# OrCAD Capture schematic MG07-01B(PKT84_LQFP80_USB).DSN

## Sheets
1 01. Adapter IF: size D; title: Adapter I/F; rev: 1.1; company: megawin; note: MG07-01
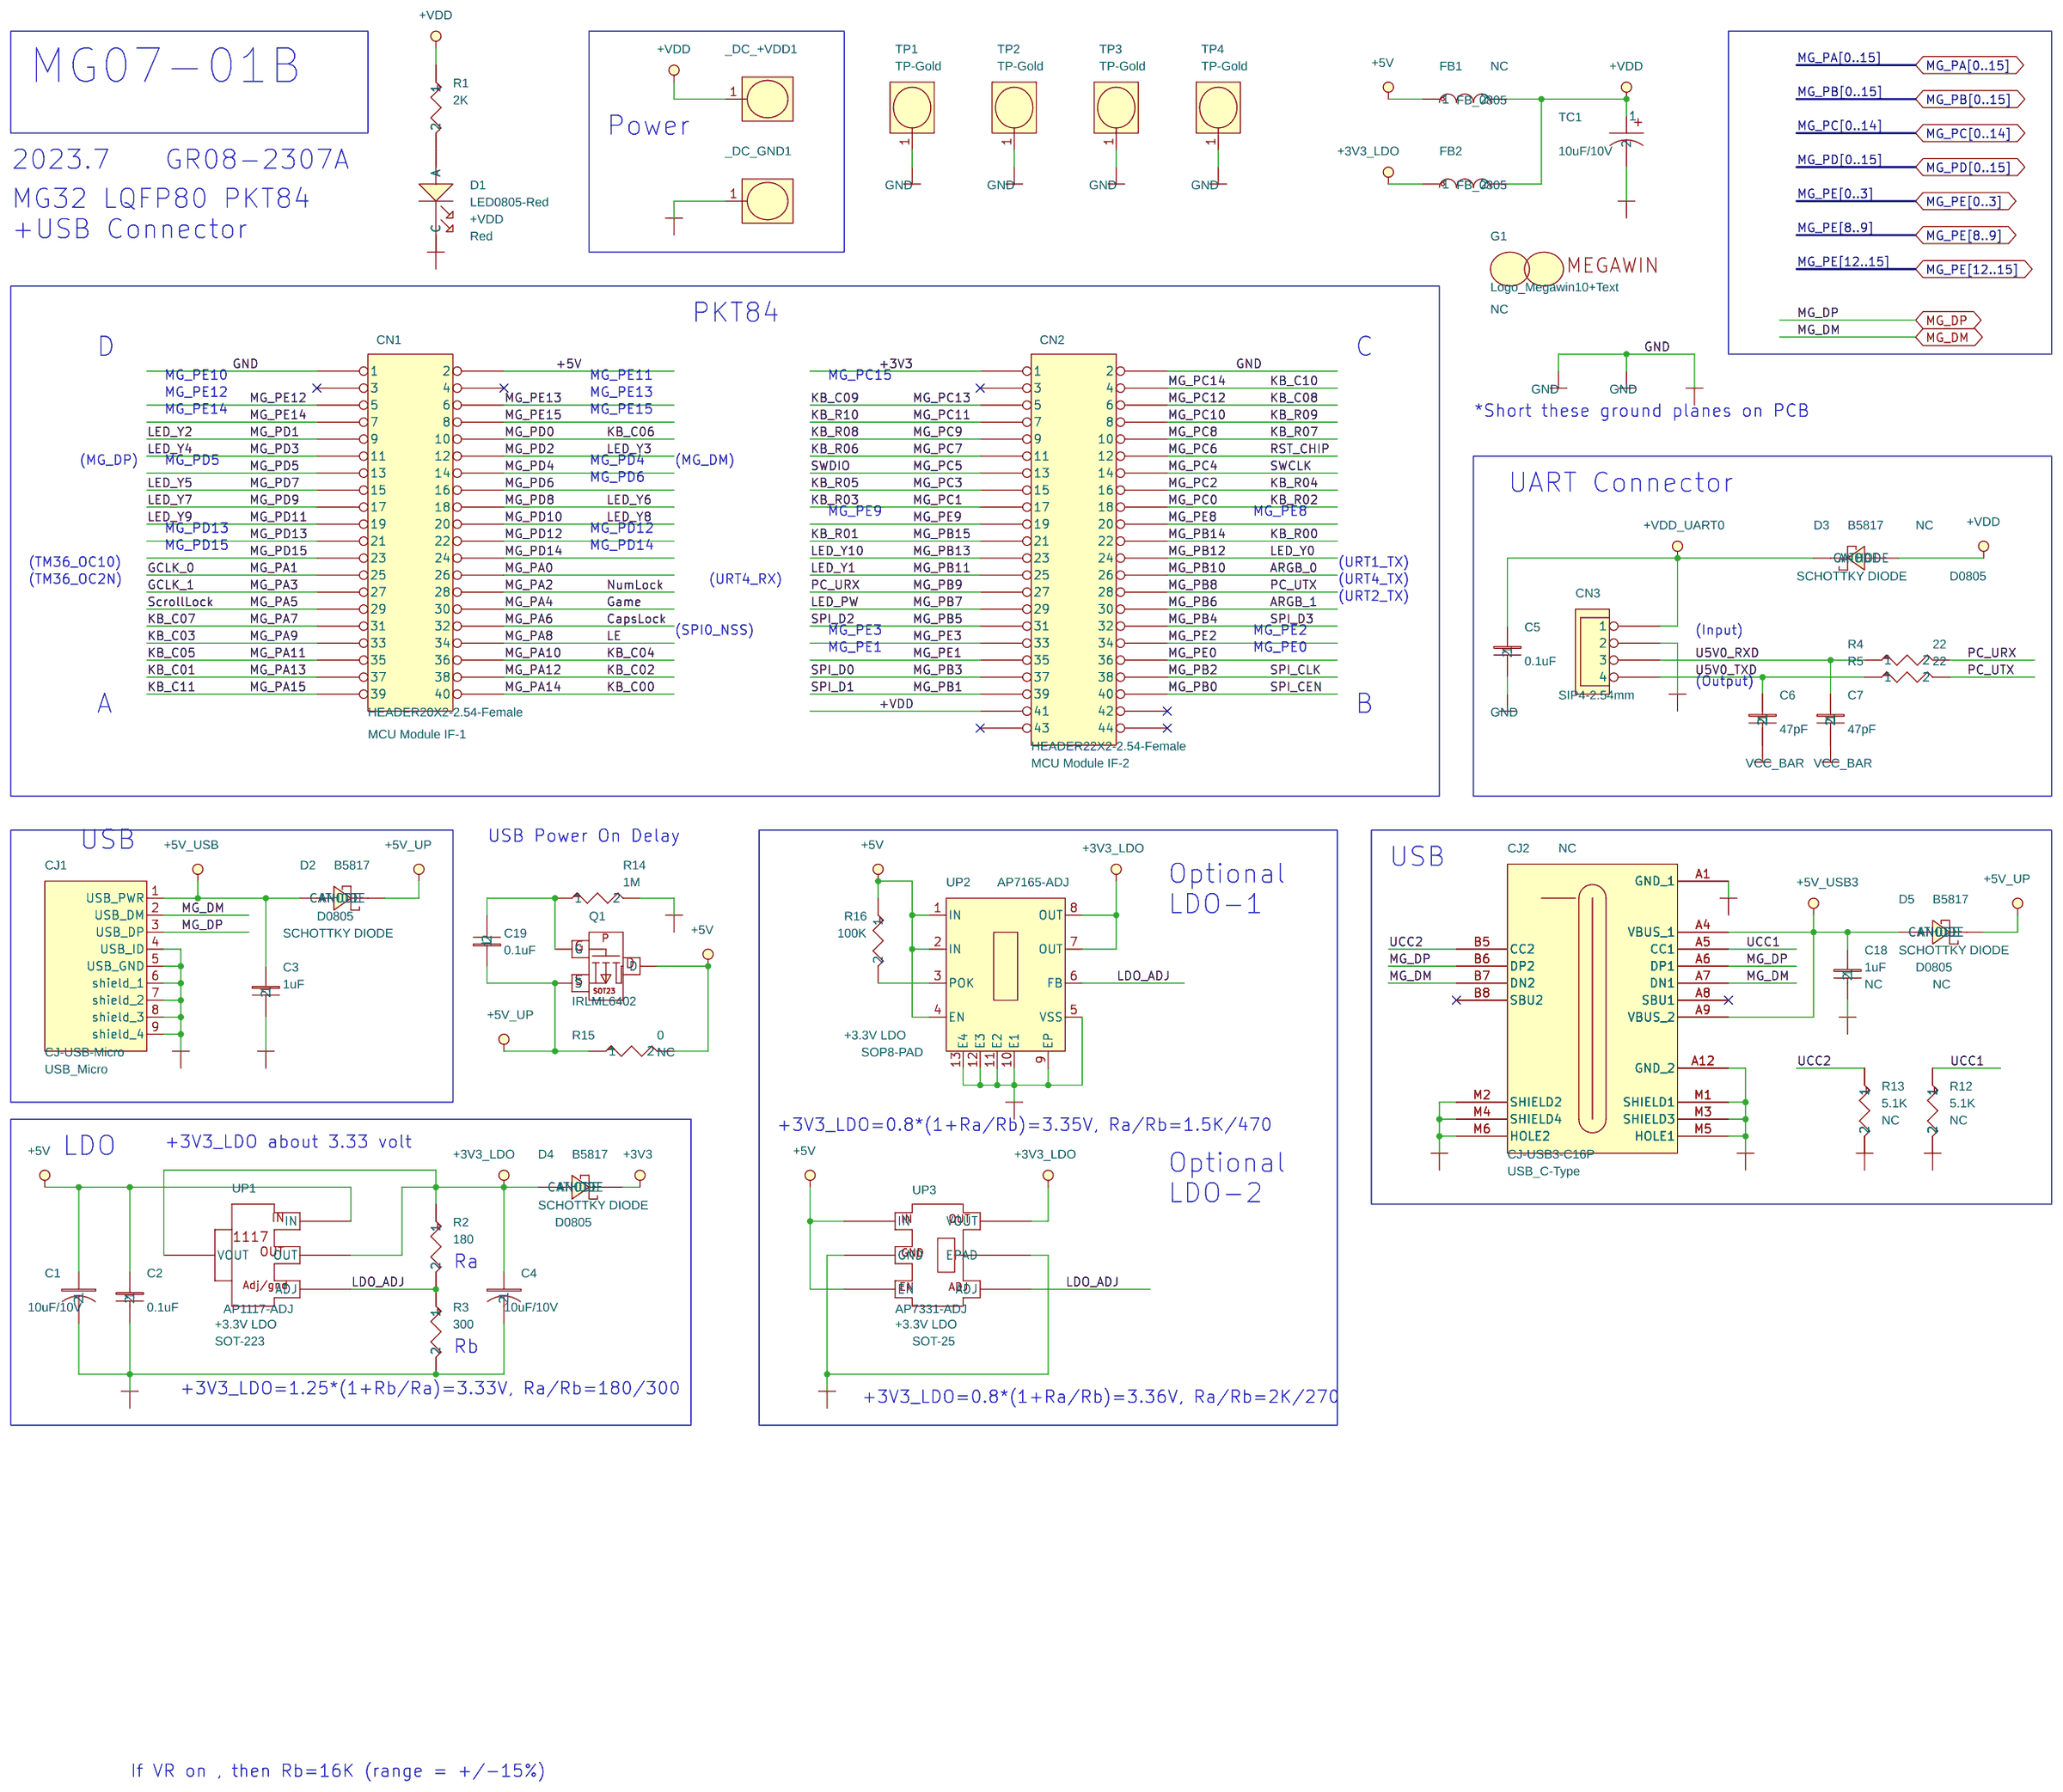
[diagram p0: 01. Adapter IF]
2 02. JA243_Main: size C; title: MCU Chip; rev: 1.0
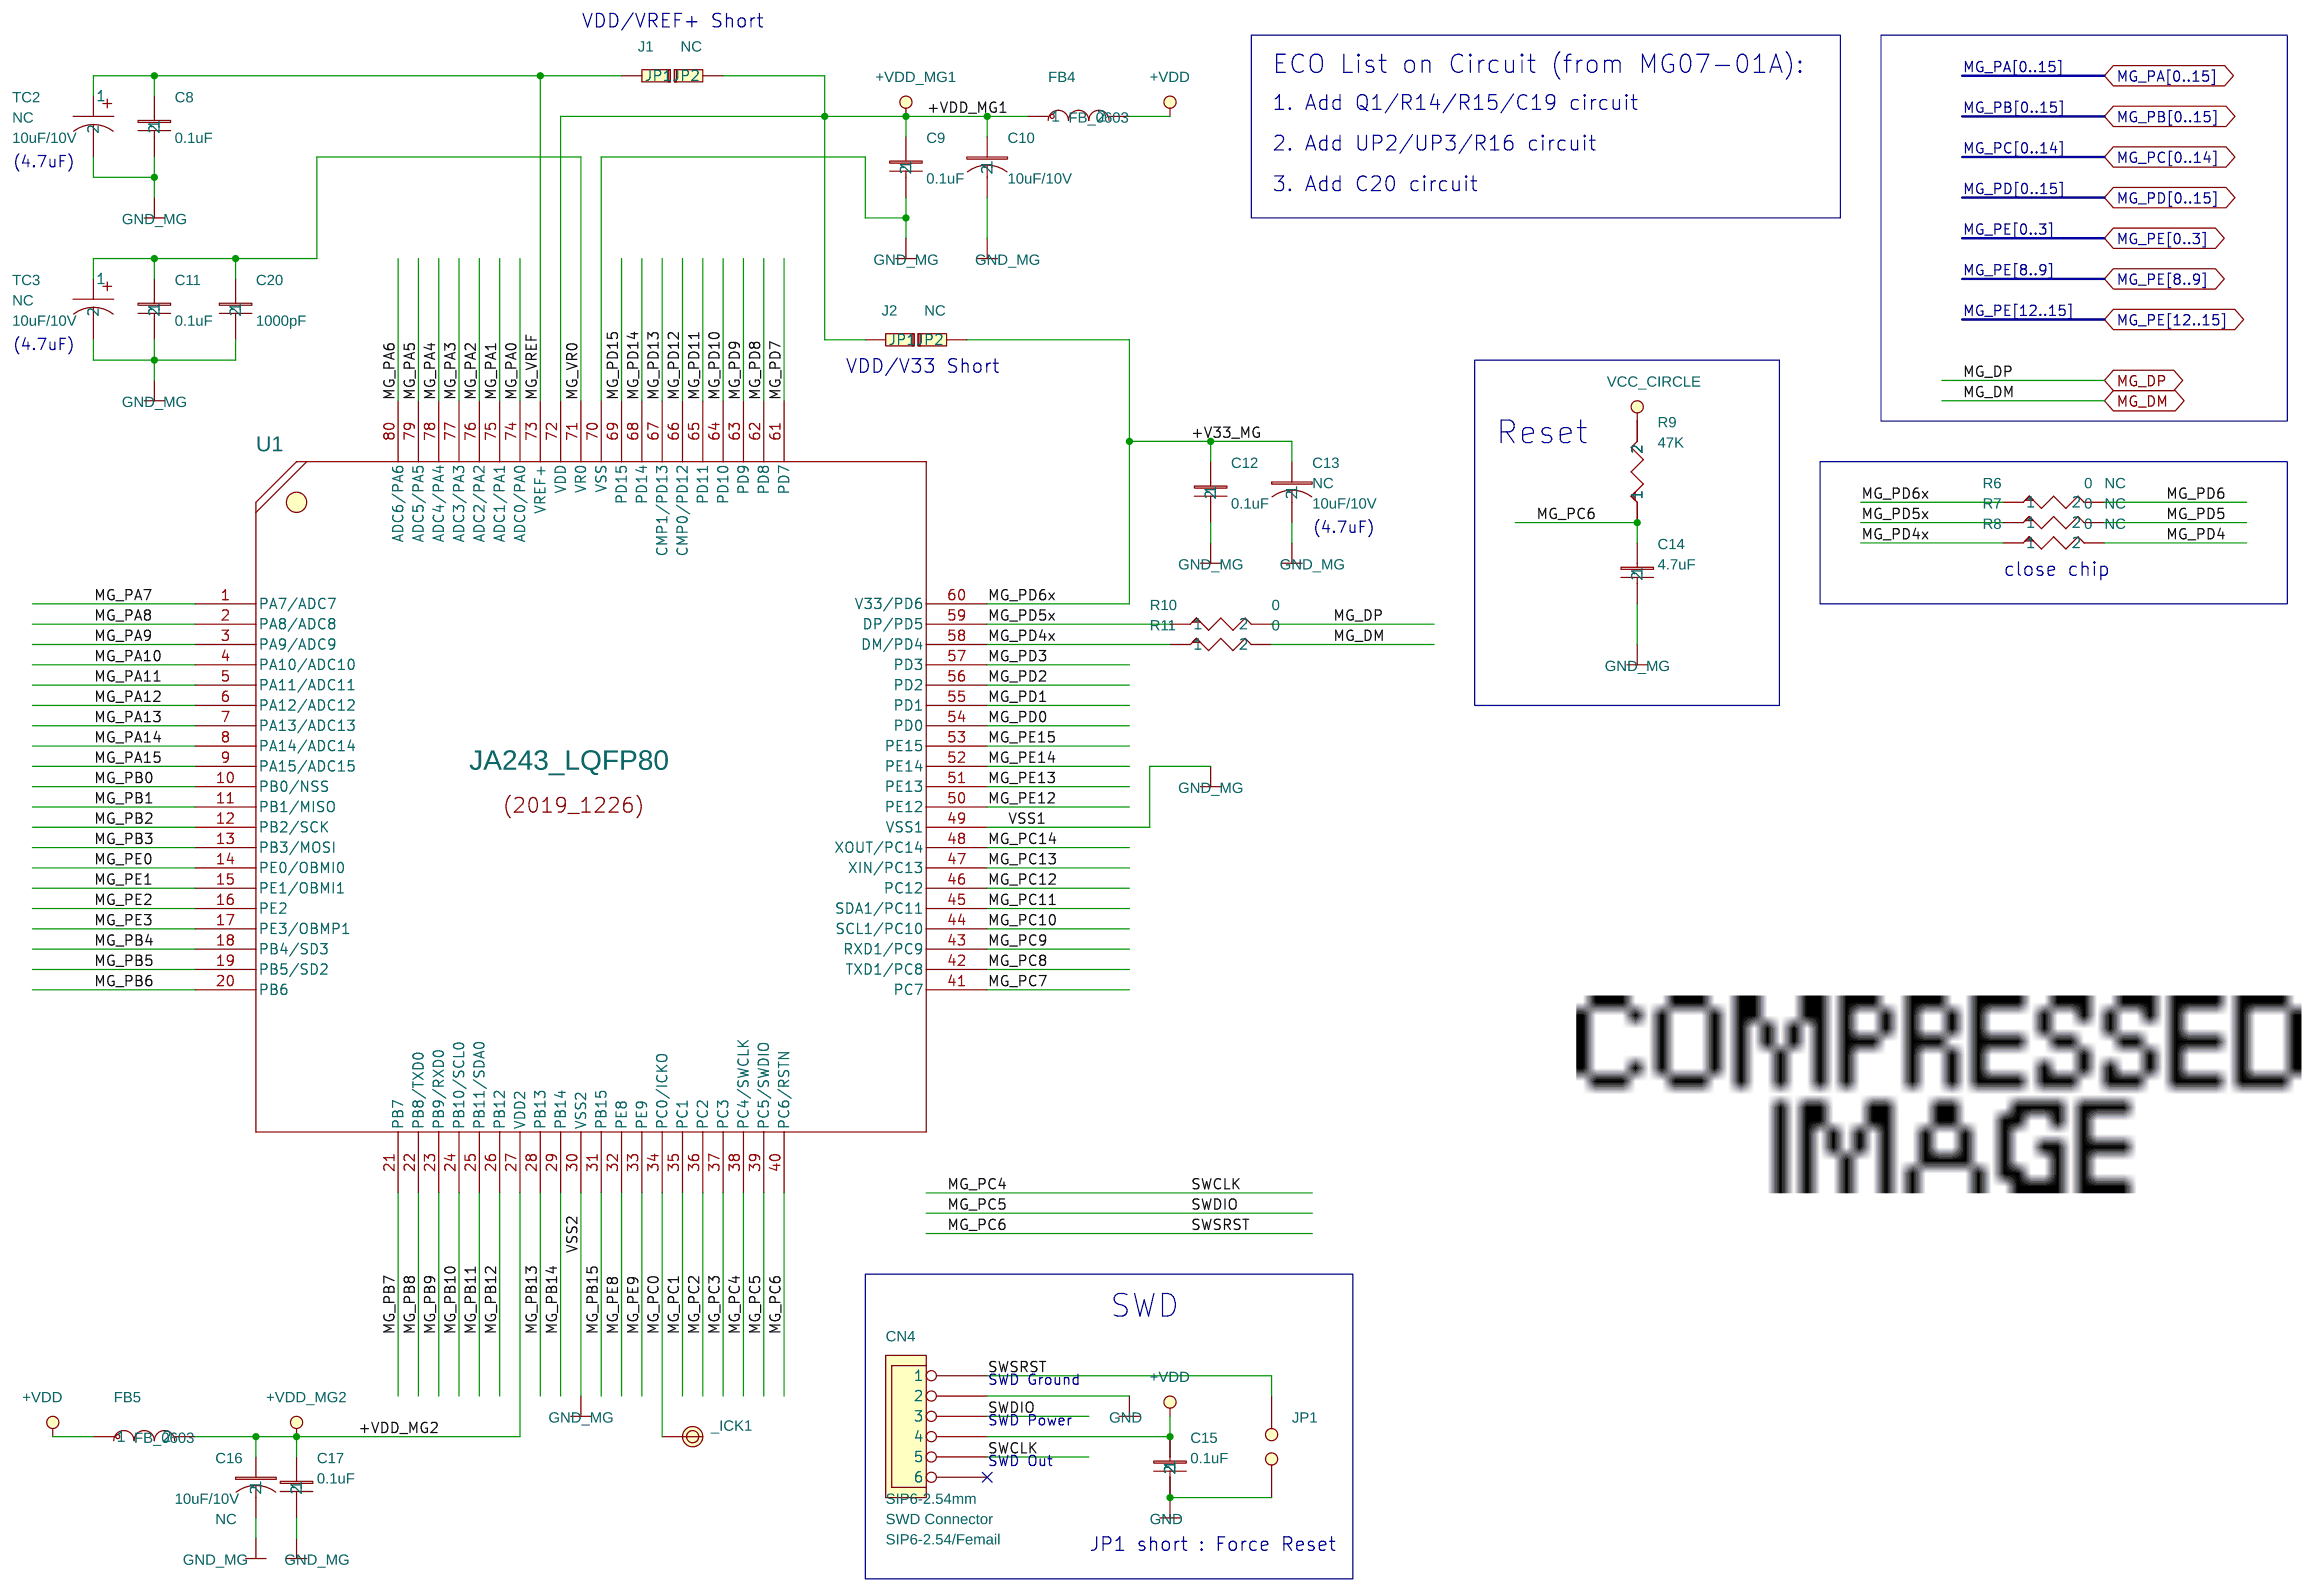
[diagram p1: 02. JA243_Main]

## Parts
sheet 01. Adapter IF
_DC_+VDD1  +5V_DC  [SIP1-50]
_DC_GND1  GND  [SIP1-50]
C1  10uF/10V  [C-0805]
C2  0.1uF  [C-0603]
C3  1uF  [C-0603]
C4  10uF/10V  [C-0805]
C5  0.1uF  [C-0603]
C6  47pF  [C-0603]
C7  47pF  [C-0603]
C18  1uF  [C-0603]
C19  0.1uF  [C-0603]
CJ1  CJ-USB-Micro  [USB5B-MICRO-7.5.X5.4P065]
CJ2  CJ-USB3-C16P  [USB16-C-C16P]
CN1  HEADER20X2-2.54-Female  [HD20X2-P2.54]
CN2  HEADER22X2-2.54-Female  [HD22X2-P2.54]
CN3  SIP4-2.54mm  [HD4-P2.54-Z12.4X5.7X7-UL]
D1  LED0805-Red  [LED-0805]
D2  B5817  [D-0805]
D3  B5817  [D-0805]
D4  B5817  [D-0805]
D5  B5817  [D-0805]
FB1  FB_0805  [L-0805]
FB2  FB_0805  [L-0805]
G1  Logo_Megawin10+Text  [MEGAWIN10_1]
Q1  IRLML6402  [SOT-23]
R1  2K  [R-0603]
R2  180  [R-0603]
R3  300  [R-0603]
R4  22  [R-0603]
R5  22  [R-0603]
R12  5.1K  [R-0603]
R13  5.1K  [R-0603]
R14  1M  [R-0603]
R15  0  [R-0603]
R16  100K  [R-0603]
TC1  10uF/10V  [C-1210+]
TP1  TP-Gold  [SIP1-39]
TP2  TP-Gold  [SIP1-39]
TP3  TP-Gold  [SIP1-39]
TP4  TP-Gold  [SIP1-39]
UP1  AP1117-ADJ  [SOT223H\3P]
UP2  AP7165-ADJ  [SOP8-P1.27-W6.2-PAD]
UP3  AP7331-ADJ  [SOT-25-PAD]
sheet 02. JA243_Main
_ICK1  TP-COIL  [TPH60-COIL]
C8  0.1uF  [C-0603]
C9  0.1uF  [C-0603]
C10  10uF/10V  [C-0805]
C11  0.1uF  [C-0603]
C12  0.1uF  [C-0603]
C13  10uF/10V  [C-0805]
C14  4.7uF  [C-0603]
C15  0.1uF  [C-0603]
C16  10uF/10V  [C-0805]
C17  0.1uF  [C-0603]
C20  1000pF  [C-0603]
CN4  SIP6-2.54mm  [HD6-P2.54-UL]
FB4  FB_0603  [L-0603]
FB5  FB_0603  [L-0603]
J1  JUNCTION_0603  [JUNCTION-0603]
J2  JUNCTION_0603  [JUNCTION-0603]
JP1  JUMPER  [SIP2-P2.54]
R6  0  [R-0603]
R7  0  [R-0603]
R8  0  [R-0603]
R9  47K  [R-0603]
R10  0  [R-0603]
R11  0  [R-0603]
TC2  10uF/10V  [C-1210+]
TC3  10uF/10V  [C-1210+]
U1  JA243_LQFP80  [QFP80-P0.4-Z12X12]

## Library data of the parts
_DC_+VDD1 _DC_GND1 = TPH-GND: Assembly: NC
C1 = CAP-POL
C2 C20 = CAP-NP_1
C3 = CAP-NP_3: 2ND PART FIELD: SMD_0805; Package: 0603 Multilayer Ceramic Chip Capacitor
C4 = CAP-POL_1: Package: 1008 Multilayer Ceramic Chip Capacitor
C5 = CAP-NP_6: Package: 0603 Multilayer Ceramic Chip Capacitor
C6 = CAP-NP: Package: 0603 Multilayer Ceramic Chip Capacitor
C7 = CAP-NP_5: Package: 0603 Multilayer Ceramic Chip Capacitor
C18 = CAP-NP_4: 2ND PART FIELD: SMD_0805; Assembly: NC; Package: 0603 Multilayer Ceramic Chip Capacitor
C14 C19 = CAP-NP_2
CJ1 = CJ-USB-Micro: Package: USB_Micro
CJ2 = CJ-USB3-C16P: Assembly: NC; Package: USB_C-Type
CN1 = HEADER20X2: Function: MCU Module IF-1; Package: HEADER20X2-2.54
CN2 = HEADER22X2: Function: MCU Module IF-2; Package: HEADER22X2-2.54
CN3 = SIP4: Package: SIP4-2.54
D1 = LED: Assembly: Red; Function: +VDD; Package: Red
D2 D4 = DIODE-SCHOTTKY-2: Function: SCHOTTKY DIODE; Package: D0805
D3 D5 = DIODE-SCHOTTKY-2: Assembly: NC; Function: SCHOTTKY DIODE; Package: D0805
FB1 = FB2_1: Assembly: NC
FB2 FB4 = FB2
G1 = LOGO-Megawin10+Text: Assembly: NC
Q1 = MOS-P-SOT23
R1 = R: 2ND PART FIELD: SMD_0805; Package: 0603 SMD Resister
R2 = R_2
R3 = R_3
R4 = R_6: Package: 0603 SMD Resister
R5 = R_4: Package: 0603 SMD Resister
R12 = R_9: Assembly: NC
R13 = R_5: Assembly: NC
R14 = R_7: 2ND PART FIELD: SMD_0805; Package: 0603 SMD Resister
R15 = R_8: 2ND PART FIELD: SMD_0805; Assembly: NC; Package: 0603 SMD Resister
R16 = R_1: 2ND PART FIELD: SMD_0805; Package: 0603 SMD Resister
TC1 = CAP-EC
TP1-TP4 = TPH-GND: Assembly: NC; Package: Gold Test Pin
UP1 = ICP-AP1117: Function: +3.3V LDO; Package: SOT-223
UP2 = ICP-AP7165: Function: +3.3V LDO; Package: SOP8-PAD
UP3 = SOT25-PAD: Function: +3.3V LDO; Package: SOT-25
_ICK1 = TPH60-COIL: Assembly: NC
C8 = CAP-NP_5
C9 = CAP-NP_6
C10 = CAP-POL_2
C11 = CAP-NP_7
C12 = CAP-NP_3
C13 = CAP-POL: Assembly: NC
C15 = CAP-NP
C16 = CAP-POL_1: Assembly: NC
C17 = CAP-NP_4
CN4 = SIP6: Function: SWD Connector; Package: SIP6-2.54/Femail
FB5 = FB2_1
J1 J2 = JUNCTION_0603: Assembly: NC
JP1 = JUMPER: Package: SIP2-RES
R6 = R_4: 2ND PART FIELD: SMD_0805; Assembly: NC; Package: 0603 SMD Resister
R7 = R_1: 2ND PART FIELD: SMD_0805; Assembly: NC; Package: 0603 SMD Resister
R8 = R: 2ND PART FIELD: SMD_0805; Assembly: NC; Package: 0603 SMD Resister
R9 = R_2: Package: 0603 SMD Resister
R10 = R_3: 2ND PART FIELD: SMD_0805; Package: 0603 SMD Resister
R11 = R_5: 2ND PART FIELD: SMD_0805; Package: 0603 SMD Resister
TC2 = CAP-EC_1: Assembly: NC
TC3 = CAP-EC: Assembly: NC
U1 = IC-MG32F02A128-LQFP80

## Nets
+3V3: CN2.1 D4.2(CATHODE)
+3V3_LDO: C4.1 D4.1(ANODE) FB2.1 R2.1 UP1.2(OUT) UP1.4(VOUT) UP2.7(OUT) UP2.8(OUT) UP3.5(VOUT)
+5V: C1.1 C2.1 CN1.2 FB1.1 Q1.3(D) R15.2 R16.1 UP1.3(IN) UP2.1(IN) UP2.2(IN) UP2.4(EN) UP3.1(IN) UP3.3(EN)
+5V_UP: C19.1 D2.2(CATHODE) D5.2(CATHODE) Q1.2(S) R15.1
+5V_USB: C3.1 CJ1.1(USB_PWR) D2.1(ANODE)
+5V_USB3: C18.1 CJ2.A4(VBUS_1) CJ2.A9(VBUS_2) D5.1(ANODE)
+V33_MG: C12.1 C13.1 J2.2(JP2) R6.1 U1.60(V33/PD6)
+VDD: _DC_+VDD1.1 C15.1 CN2.41 CN4.4 D3.1(ANODE) FB1.2 FB2.2 FB4.2 FB5.1 R1.1 TC1.1
+VDD_MG1: C9.1 C10.1 FB4.1 J1.2(JP2) J2.1(JP1) U1.72(VDD)
+VDD_MG2: C16.1 C17.1 FB5.2 R9.2 U1.27(VDD2)
+VDD_UART0: C5.1 CN3.1 D3.2(CATHODE)
GND_MG: _DC_GND1.1 C1.2 C2.2 C3.2 C4.2 C5.2 C6.2 C7.2 C8.2 C9.2 C10.2 C11.2 C12.2 C13.2 C14.2 C15.2 C16.2 C17.2 C18.2 C20.2 CJ1.4(USB_ID) CJ1.5(USB_GND) CJ1.6(shield_1) CJ1.7(shield_2) CJ1.8(shield_3) CJ1.9(shield_4) CJ2.A1(GND_1) CJ2.A12(GND_2) CJ2.M1(SHIELD1) CJ2.M2(SHIELD2) CJ2.M3(SHIELD3) CJ2.M4(SHIELD4) CJ2.M5(HOLE1) CJ2.M6(HOLE2) CN1.1 CN2.2 CN3.2 CN4.2 D1.2(C) JP1.2 R3.2 R12.2 R13.2 R14.2 TC1.2 TC2.2 TC3.2 TP1.1 TP2.1 TP3.1 TP4.1 U1.30(VSS2) U1.49(VSS1) U1.70(VSS) UP2.5(VSS) UP2.9(EP) UP2.10(E1) UP2.11(E2) UP2.12(E3) UP2.13(E4) UP3.2(GND) UP3.6(EPAD)
LDO_ADJ: R2.2 R3.1 UP1.1(ADJ) UP2.6(FB) UP3.4(ADJ)
MG_DM: CJ1.2(USB_DM) CJ2.A7(DN1) CJ2.B7(DN2) R11.2
MG_DP: CJ1.3(USB_DP) CJ2.A6(DP1) CJ2.B6(DP2) R10.2
MG_PA0: CN1.26 U1.74(ADC0/PA0)
MG_PA1: CN1.25 U1.75(ADC1/PA1)
MG_PA2: CN1.28 U1.76(ADC2/PA2)
MG_PA3: CN1.27 U1.77(ADC3/PA3)
MG_PA4: CN1.30 U1.78(ADC4/PA4)
MG_PA5: CN1.29 U1.79(ADC5/PA5)
MG_PA6: CN1.32 U1.80(ADC6/PA6)
MG_PA7: CN1.31 U1.1(PA7/ADC7)
MG_PA8: CN1.34 U1.2(PA8/ADC8)
MG_PA9: CN1.33 U1.3(PA9/ADC9)
MG_PA10: CN1.36 U1.4(PA10/ADC10)
MG_PA11: CN1.35 U1.5(PA11/ADC11)
MG_PA12: CN1.38 U1.6(PA12/ADC12)
MG_PA13: CN1.37 U1.7(PA13/ADC13)
MG_PA14: CN1.40 U1.8(PA14/ADC14)
MG_PA15: CN1.39 U1.9(PA15/ADC15)
MG_PB0: CN2.40 U1.10(PB0/NSS)
MG_PB1: CN2.39 U1.11(PB1/MISO)
MG_PB2: CN2.38 U1.12(PB2/SCK)
MG_PB3: CN2.37 U1.13(PB3/MOSI)
MG_PB4: CN2.32 U1.18(PB4/SD3)
MG_PB5: CN2.31 U1.19(PB5/SD2)
MG_PB6: CN2.30 U1.20(PB6)
MG_PB7: CN2.29 U1.21(PB7)
MG_PB8: CN2.28 R5.2 U1.22(PB8/TXD0)
MG_PB9: CN2.27 R4.2 U1.23(PB9/RXD0)
MG_PB10: CN2.26 U1.24(PB10/SCL0)
MG_PB11: CN2.25 U1.25(PB11/SDA0)
MG_PB12: CN2.24 U1.26(PB12)
MG_PB13: CN2.23 U1.28(PB13)
MG_PB14: CN2.22 U1.29(PB14)
MG_PB15: CN2.21 U1.31(PB15)
MG_PC0: _ICK1.1 CN2.18 U1.34(PC0/ICKO)
MG_PC1: CN2.17 U1.35(PC1)
MG_PC2: CN2.16 U1.36(PC2)
MG_PC3: CN2.15 U1.37(PC3)
MG_PC4: CN2.14 CN4.5 U1.38(PC4/SWCLK)
MG_PC5: CN2.13 CN4.3 U1.39(PC5/SWDIO)
MG_PC6: C14.1 CN2.12 CN4.1 JP1.1 R9.1 U1.40(PC6/RSTN)
MG_PC7: CN2.11 U1.41(PC7)
MG_PC8: CN2.10 U1.42(TXD1/PC8)
MG_PC9: CN2.9 U1.43(RXD1/PC9)
MG_PC10: CN2.8 U1.44(SCL1/PC10)
MG_PC11: CN2.7 U1.45(SDA1/PC11)
MG_PC12: CN2.6 U1.46(PC12)
MG_PC13: CN2.5 U1.47(XIN/PC13)
MG_PC14: CN2.4 U1.48(XOUT/PC14)
MG_PD0: CN1.10 U1.54(PD0)
MG_PD1: CN1.9 U1.55(PD1)
MG_PD2: CN1.12 U1.56(PD2)
MG_PD3: CN1.11 U1.57(PD3)
MG_PD4: CN1.14 R8.2
MG_PD4x: R8.1 R11.1 U1.58(DM/PD4)
MG_PD5: CN1.13 R7.2
MG_PD5x: R7.1 R10.1 U1.59(DP/PD5)
MG_PD6: CN1.16 R6.2
MG_PD7: CN1.15 U1.61(PD7)
MG_PD8: CN1.18 U1.62(PD8)
MG_PD9: CN1.17 U1.63(PD9)
MG_PD10: CN1.20 U1.64(PD10)
MG_PD11: CN1.19 U1.65(PD11)
MG_PD12: CN1.22 U1.66(CMP0/PD12)
MG_PD13: CN1.21 U1.67(CMP1/PD13)
MG_PD14: CN1.24 U1.68(PD14)
MG_PD15: CN1.23 U1.69(PD15)
MG_PE0: CN2.36 U1.14(PE0/OBMI0)
MG_PE1: CN2.35 U1.15(PE1/OBMI1)
MG_PE2: CN2.34 U1.16(PE2)
MG_PE3: CN2.33 U1.17(PE3/OBMP1)
MG_PE8: CN2.20 U1.32(PE8)
MG_PE9: CN2.19 U1.33(PE9)
MG_PE12: CN1.5 U1.50(PE12)
MG_PE13: CN1.6 U1.51(PE13)
MG_PE14: CN1.7 U1.52(PE14)
MG_PE15: CN1.8 U1.53(PE15)
MG_VR0: C11.1 C20.1 TC3.1 U1.71(VR0)
MG_VREF: C8.1 J1.1(JP1) TC2.1 U1.73(VREF+)
U5V0_RXD: C7.1 CN3.3 R4.1
U5V0_TXD: C6.1 CN3.4 R5.1
UCC1: CJ2.A5(CC1) R12.1
UCC2: CJ2.B5(CC2) R13.1
N65855923: C19.2 Q1.1(G) R14.1
N65861385: R16.2 UP2.3(POK)
N65862524: D1.1(A) R1.2

Not connected (* = marked no-connect by the designer): CJ2 A8(SBU1)* B8(SBU2)*; CN1 3* 4*; CN2 3* 42* 43* 44*; CN4 6*; G1 1(.)

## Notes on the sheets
sheet 1
- MG07-01B
- Power
- 2023.7
- GR08-2307A
- MG32 LQFP80 PKT84
  +USB Connector
- PKT84
- D
- C
- MG_PE10
- MG_PE11
- MG_PC15
- MG_PE12
- MG_PE13
- MG_PE14
- MG_PE15
- *Short these ground planes on PCB
- (MG_DP)
- MG_PD5
- MG_PD4
- (MG_DM)
- MG_PD6
- UART Connector
- MG_PD13
- MG_PD12
- MG_PE9
- MG_PE8
- MG_PD15
- MG_PD14
- (TM36_OC10)
- (URT1_TX)
- (TM36_OC2N)
- (URT4_RX)
- (URT4_TX)
- (URT2_TX)
- (SPI0_NSS)
- MG_PE1
- MG_PE3
- MG_PE0
- MG_PE2
- (Input)
- (Output)
- A
- B
- USB
- USB Power On Delay
- Optional
  LDO-1
- USB
- +3V3_LDO=0.8*(1+Ra/Rb)=3.35V, Ra/Rb=1.5K/470
- LDO
- +3V3_LDO about 3.33 volt
- Optional
  LDO-2
- Ra
- Rb
- +3V3_LDO=1.25*(1+Rb/Ra)=3.33V, Ra/Rb=180/300
- +3V3_LDO=0.8*(1+Ra/Rb)=3.36V, Ra/Rb=2K/270
- If VR on , then Rb=16K (range = +/-15%)
sheet 2
- VDD/VREF+ Short
- ECO List on Circuit (from MG07-01A):
- 1. Add Q1/R14/R15/C19 circuit
- 2. Add UP2/UP3/R16 circuit
- (4.7uF)
- 3. Add C20 circuit
- (4.7uF)
- VDD/V33 Short
- Reset
- (4.7uF)
- close chip
- SWD
- SWD Ground
- SWD Power
- SWD Out
- JP1 short : Force Reset
